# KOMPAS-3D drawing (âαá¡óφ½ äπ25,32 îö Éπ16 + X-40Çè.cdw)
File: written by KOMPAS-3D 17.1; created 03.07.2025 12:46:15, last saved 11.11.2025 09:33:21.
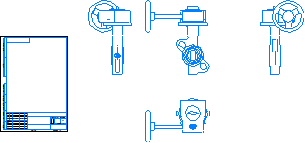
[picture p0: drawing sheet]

Sheet 1: A4, portrait

Title block, sheet 1: sheets: 1; sheet format: A4; stored path: \\adlc.lan\data\АДЛ_ПКД\3D-модели\ADL production\Дисковые поворотные затворы ГРАНВЭЛ\межфланцевый с китайским редуктором Ру16\KOMPAS 2D\Гранвэл Ду25,32 МФ Ру16 + X-40АК.cdw

Views: Вид 1, Спереди, Проекционный вид 2, Проекционный вид 3, Проекционный вид 4
Referenced files in \\adlc.lan\data\АДЛ_ПКД\3D-модели\ADL production\Дисковые поворотные затворы ГРАНВЭЛ\межфланцевый с китайским редуктором Ру16\KOMPAS 3D\: Гранвэл Ду25,32 МФ Ру16 + X-40АК.m3d
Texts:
  Andrey
  АДЛ
Dimensions and other numbers on the sheet: 1:1; 1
